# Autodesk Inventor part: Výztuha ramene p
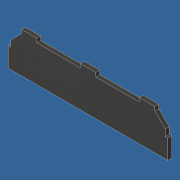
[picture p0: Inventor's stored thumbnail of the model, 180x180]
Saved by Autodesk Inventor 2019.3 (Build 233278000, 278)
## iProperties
Created: 2019-02
Part Number: Výztuha ramene p
Material: Nerezová ocel, austenitická
Document SubType Name: Modeling
Designer: B-hon
Density: 8 g/cm^3
Appearance: Tmavě šedá
Author: B-hon
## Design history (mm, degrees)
sketch "Náčrt1"
  geometry: L1 (0, 0)-(123, 0); L2 (123, 0)-(123, 31); L3 (123, 31)-(0, 31); L4 (0, 31)-(0, 0)
  constraints: 8 end point, 2 parallel, 1 horizontal, 1 perpendicular
  dimensions: "d0" = 123 distance of L3.end L2.end; "d1" = 31 distance of L2.end L1.end
extrude "Vysunutí1" new body sketch "Náčrt1" distance "d2" = 3; taper "d3" = 0 deg
sketch "Náčrt2"
  geometry: L1 (-5.629, 40.214)-(2, 40.214); L2 (2, 40.214)-(2, 15); L3 (2, 15)-(-5.629, 15); L4 (-5.629, 15)-(-5.629, 40.214); L5 (0, 0)-(123, 0) reference; L6 (0, 31)-(0, 0) reference; L7 (121, 47.584)-(218.204, 47.584); L8 (218.204, 47.584)-(218.204, 15); L9 (218.204, 15)-(121, 15); L10 (121, 15)-(121, 47.584); L11 (123, 0)-(123, 31) reference
  constraints: 16 end point, 4 parallel, 2 horizontal, 2 perpendicular
  dimensions: "d4" = 15 distance between parallel lines of L5 L3; "d5" = 2 distance between parallel lines of L6 L2; "d6" = 15 distance between parallel lines of L5 L9; "d7" = 2 distance between parallel lines of L11 L10
extrude "Vysunutí2" cut sketch "Náčrt2" distance "d8" = 3; taper "d9" = 0 deg
sketch "Náčrt3"
  geometry: L1 (101, 44.218)-(67.5, 44.218); L2 (67.5, 44.218)-(67.5, 28); L3 (67.5, 28)-(101, 28); L4 (101, 28)-(101, 44.218); L5 (55.5, 39.969)-(22, 39.969); L6 (22, 39.969)-(22, 28); L7 (22, 28)-(55.5, 28); L8 (55.5, 28)-(55.5, 39.969); L9 (123, 0)-(123, 15) reference; L10 (121, 31)-(2, 31) reference; L11 (0, 15)-(0, 0) reference; L12 (2, 31)-(2, 15) reference
  constraints: 16 end point, 4 parallel, 2 horizontal, 2 perpendicular
  dimensions: "d11" = 3 distance between parallel lines of L10 L3; "d12" = 33.5 distance of L2.end L3.end; "d14" = 33.5 distance of L6.end L7.end; "d15" = 3 distance between parallel lines of L10 L7; "d26" = 12 distance between parallel lines of L2 L8; "d27" = 20 distance between parallel lines of L12 L6
extrude "Vysunutí3" cut sketch "Náčrt3" distance "d16" = 3; taper "d17" = 0 deg
sketch "Náčrt4"
  geometry: L1 (-11.66, 39.496)-(10, 39.496); L2 (10, 39.496)-(10, 28); L3 (10, 28)-(-11.66, 28); L4 (-11.66, 28)-(-11.66, 39.496); L5 (218.41, 46.602)-(113, 46.602); L6 (113, 46.602)-(113, 28); L7 (113, 28)-(218.41, 28); L8 (218.41, 28)-(218.41, 46.602); L9 (22, 31)-(2, 31) reference; L10 (22, 28)-(22, 31) reference; L11 (101, 31)-(101, 28) reference; 1 further point
  constraints: 16 end point, 4 parallel, 2 horizontal, 2 perpendicular, 1 point on line
  dimensions: "d18" = 3 distance between parallel lines of L9 L3; "d19" = 12 distance between parallel lines of L10 L2; "d20" = 12 distance between parallel lines of L11 L6
extrude "Vysunutí4" cut sketch "Náčrt4" distance "d21" = 3; taper "d22" = 0 deg
chamfer "Zkosení2" distance "d28" = 8; stored, may be unused: second distance "d29" = 2, angle "d30" = 45 deg
node "Těleso1"
